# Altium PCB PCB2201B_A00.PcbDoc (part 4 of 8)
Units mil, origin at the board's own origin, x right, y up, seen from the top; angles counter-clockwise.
Board outline 4523.63 x 2358.23 mil, 6 copper layers (Top Layer, Signal Layer 2, Signal Layer 3, Signal Layer 4, Signal Layer 5, Bottom Layer), stack 61.221 mil thick; 383 components, 308 nets, 1386 pads, 1147 vias.
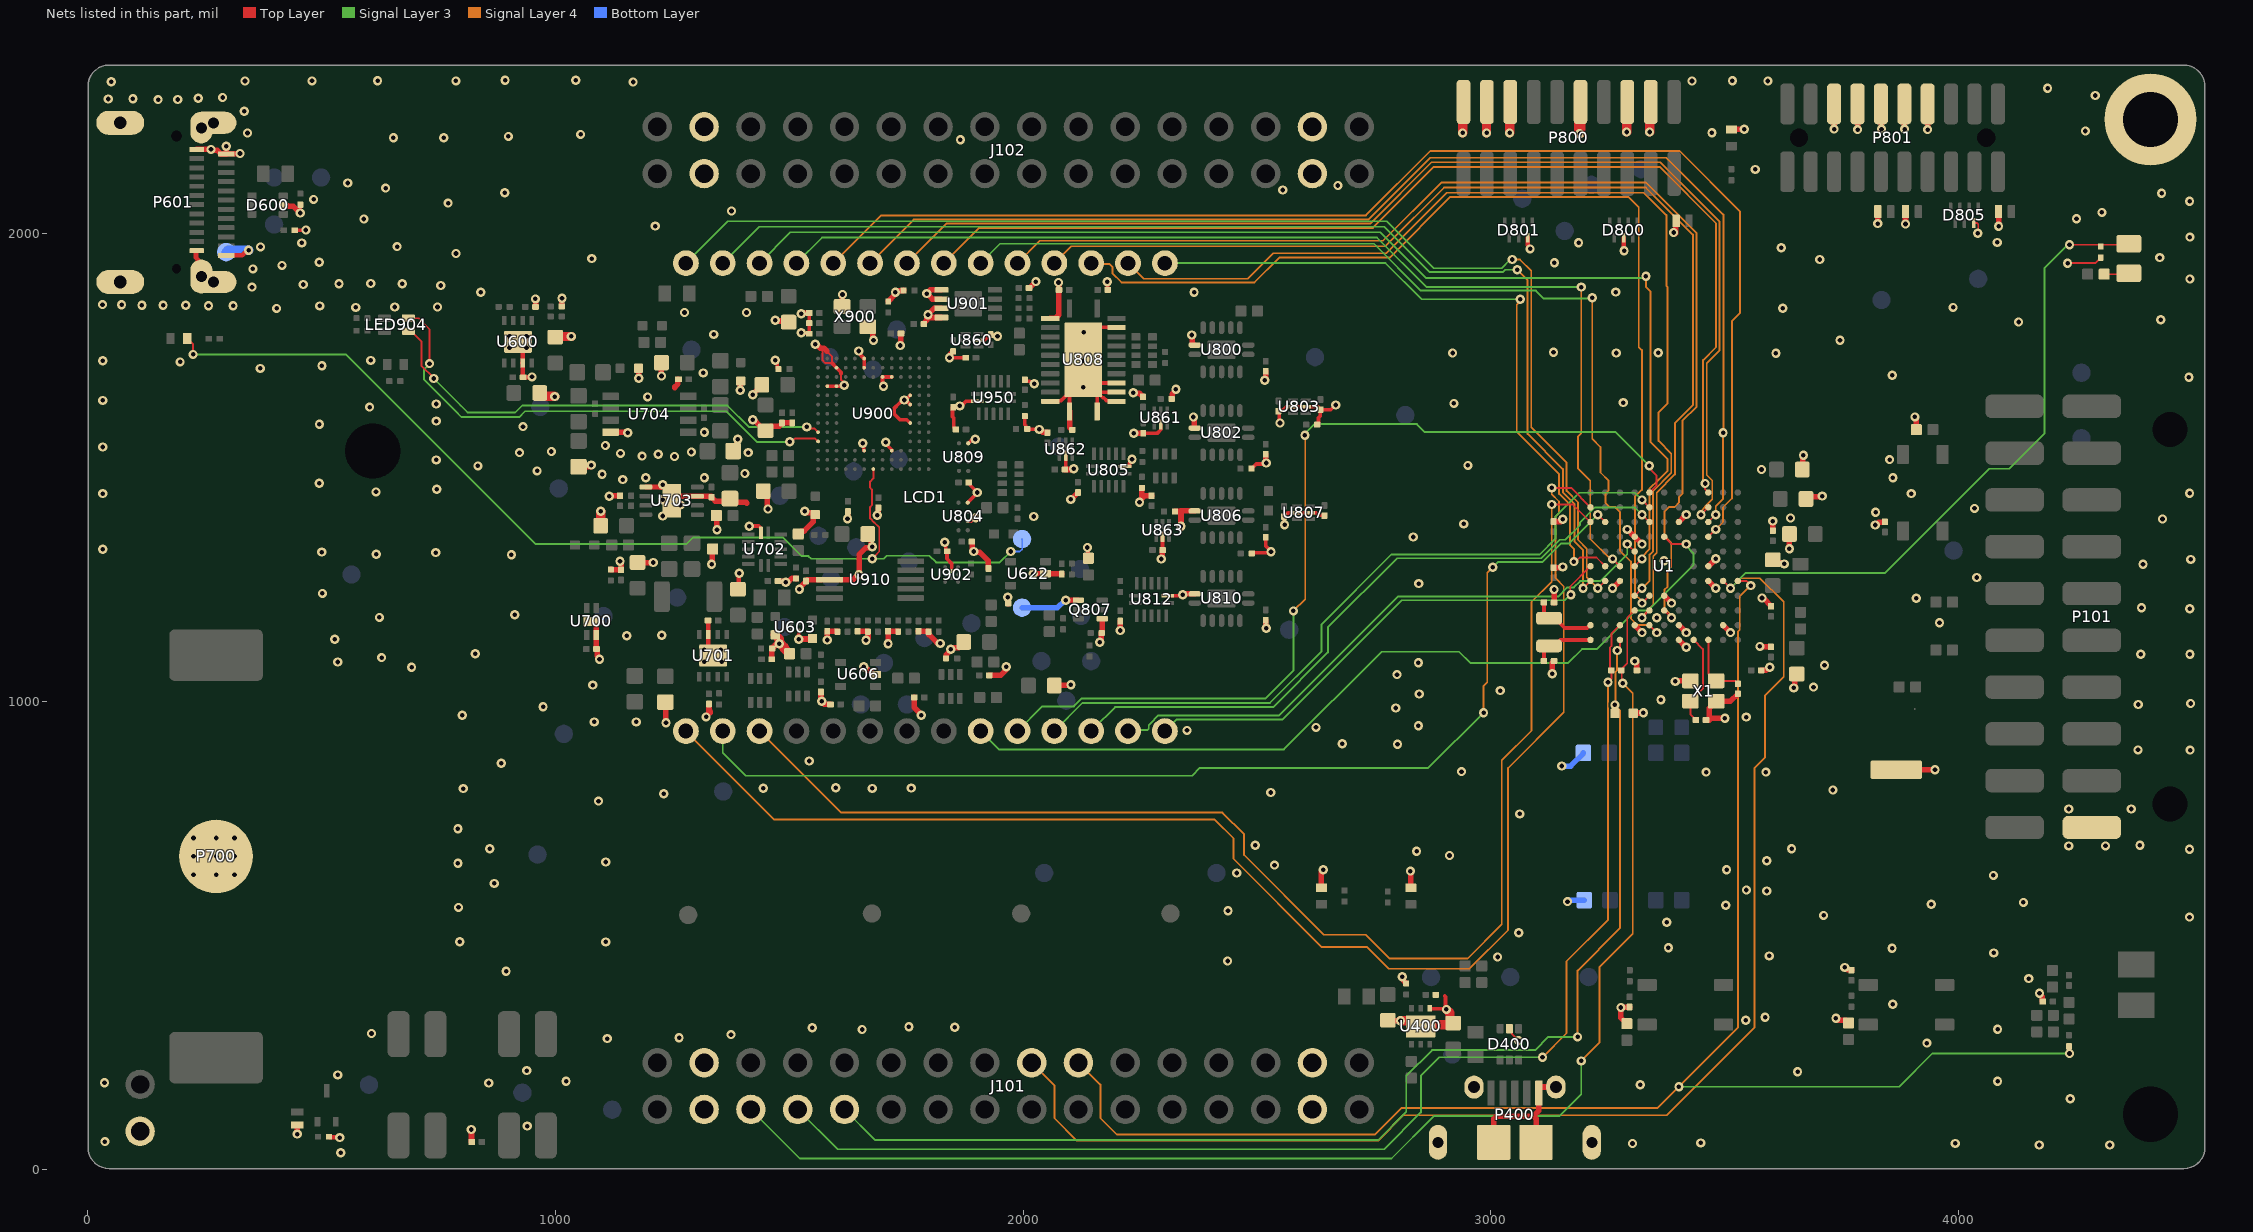
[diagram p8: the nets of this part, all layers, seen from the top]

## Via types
v1: diameter 19.68, hole 9.84, Top Layer to Bottom Layer, tented both sides, 768 vias
v2: diameter 20, hole 9.84, Top Layer to Bottom Layer, tented both sides, 379 vias

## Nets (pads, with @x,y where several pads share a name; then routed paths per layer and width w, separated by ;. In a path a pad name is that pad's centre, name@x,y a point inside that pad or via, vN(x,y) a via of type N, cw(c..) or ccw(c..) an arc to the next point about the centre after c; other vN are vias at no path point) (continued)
GND: C3.2 C4.2 C5.2 C6.2 C8.2 C9.2 C10.2 C13.2 C14.2 C15.2 C16.2 C40.2 C102.2 C103.2 C199.2 C200.2 C401.2 C402.2 C417.2 C418.2 C419.2 C420.2 C421.2 C422.2 C423.2 C600.2 C602.2 C607.2 C608.2 C609.2 C610.2 C611.2 C621.2 C625.2 C632.2 C635.2 C638.2 C641.2 C652.2 C653.2 C655.2 C660.2 C673.2 C674.2 C700.2 C701.2 C702.2 C703.2 C705.2 C706.2 C707.2 C708.2 C714.2 C720.2 C724.2 C728.2 C729.2 C730.2 C731.2 C800.2 C803.2 C804.2 C805.2 C806.2 C807.2 C808.2 C809.2 C810.2 C827.2 C828.2 C860.2 C861.2 C862.2 C863.2 C864.2 C865.2 C866.2 C867.2 C868.2 C869.2 C870.2 C900.2 C901.2 C902.2 C903.2 C904.2 C905.2 C906.2 C907.2 C908.2 C909.2 C910.2 C911.2 C914.2 C921.2 C922.2 C924.2 C925.2 C926.2 C927.2 C950.2 C951.2 D400.2 D600.2 D703.2 D800.6 D801.7 D805.7 D806.2 D807.2 D808.2 D809.2 J101.3 J101.4 J101.29 J101.30 J102.3 J102.4 J102.29 J102.30 LED100.2 LED101.2 LED900.2 M1.1 P101.1 P400.5 P400.6 P400.7 P400.8 P400.9 P400.10 P400.11 P601.25@70.87,2237.01 P601.26@70.87,1896.85 P601.27@244.09,2225.39 P601.27@269.69,2237.01 P601.28@244.09,1908.46 P601.28@269.69,1896.85 P601.A1 P601.A12 P601.B1 P601.B12 P700.2 P800.3 P800.5 P800.9 P800.15 P800.17 P800.19 P801.7 P801.9 P801.11 P801.13 P801.15 Q807.1 Q807.4 R7.1 R104.2 R105.2 R199.2 R240.1 R244.1 R407.1 R602.1 R620.1 R621.1 R623.1 R628.2 R631.1 R634.1 R637.1 R640.1 R674.2 R688.2 R691.2 R703.1 R705.1 R706.1 R707.1 R708.1 R718.1 R760.1 R763.1 R767.1 R771.1 R792.1 R807.2 R808.2 R814.1 R817.1 R839.1 R850.1 R851.1 R852.1 R853.1 R930.2 R931.2 R950.2 R981.2 ST701.1 TPJ614.1 TPJ913.1 U1.C7 U1.D4 U1.F9 U1.G3 U1.G9 U1.H6 U1.K4 U1.K7 U1.K10 U1.L7 U400.1 U400.7 U600.3 U600.9 U603.A1 U606.2 U622.2 U700.2 U700.5 U701.3 U701.9 U702.7 U703.3 U703.5 U703.9 U704.4 U800.7 U802.7 U803.2 U803.5 U804.B1 U804.D1 U805.7 U806.7 U807.2 U807.5 U808.2 U808.11 U808.12 U808.13 U808.14 U808.15 U808.16 U808.22 U808.25 U809.D1 U810.7 U812.7 U860.2 U861.2 U862.2 U863.2 U900.C5 U900.C8 U900.F3 U900.H3 U900.J3 U900.K11 U900.K12 U900.L5 U900.L6 U900.M8 U900.M11 U900.N8 U901.1 U901.2 U901.3 U901.4 U902.B2 U910.3 U950.7 X1.2 X1.4 X900.2 X900.4 | length 9025.5
  Top Layer w3.94: 1571.85,1752.95 1571.85,1729.19 1577.62,1723.43 1585.77,1723.43 1591.54,1723.43 ; 1580.71,1749.02 1591.54,1738.19 1591.54,1729.19 ; C638.2@1581.69,1150.59 C638.2@1582.19,1150.1 ; R637.1@1602.85,1150.1 1603.05,1150.3 R637.1@1603.35,1150.59 ; 1611.22,1700.76 1611.22,1687.44 1618.05,1680.61 v2(1618.05,1676.26) ; v1(3189.42,2213.38) 3189.42,2215.34 v1@3189.62,2215.54 ; D805.7@4031.5,2023.03 4032.87,2023.03 4033.27,2022.64 4039.17,2022.64 4041.48,2020.33 4041.48,2002.11 v1(4040.35,2000.98) ; 1591.54,1723.43 1591.54,1729.19 ; 1591.54,1723.43 1591.54,1729.19
  Top Layer w4: C423.2@2779.72,318.98 2780.3,318.41 2780.87,317.83 v1(2806.65,317.83) ; D400.2@3039.37,301.18 3044.73,295.82 3044.73,289.91 v1(3059.05,275.59) ; v1(4232.28,1937.01) 4291.34,1937.01 R199.2@4303.15,1948.82
  Top Layer w7.87: R621.1@443.71,2007.35 467,2007.35 v1(467.52,2007.87) ; v1(455.43,2044.1) 455.57,2044.24 455.57,2061.87 R620.1@455.71,2062.01 ; v2(1414.97,1375.16) 1415.09,1375.28 1435.35,1375.28 1439.96,1370.67 U702.7@1439.96,1360.63 ; C900.2@1441.93,1677.17 C900.2@1443.9,1677.17 ; v2(1470.47,1729.33) 1470.47,1726.05 1474.61,1721.92 1474.61,1712.99 1476.97,1710.63 R763.1@1477.36,1710.63 ; U603.A1@1520.67,1151.57 1520.44,1151.35 1520.44,1142.77 1519.69,1142.01 1519.69,1132.94 v2(1521.07,1132.94) ; v2(1526.1,1787.95) 1526.99,1787.07 1542.38,1787.07 C904.2@1543.27,1786.18 C905.2@1543.27,1808.86 C906.2@1543.27,1830.47 ; U900.K12@1581.69,1674.21 U900.K11@1601.38,1674.21 1616.01,1674.21 v2(1618.05,1676.26) ; 1591.54,1723.43 U900.M11@1601.38,1713.58 1611.22,1703.74 1611.22,1700.76 ; v2(1648.86,1749.2) 1647.64,1750.42 1645.79,1750.42 1645.79,1747.91 U900.N8@1660.43,1733.27 U900.M8@1660.43,1713.58 ; v2(1657.48,1552.17) 1659.8,1549.85 1659.8,1537.05 U900.C8@1660.43,1536.42 ; v2(1701.77,1674.21) 1699.8,1676.18 U900.L6@1699.8,1693.9 U900.L5@1719.49,1693.9 ; v2(1706.59,1554.29) 1706.59,1551.01 1719.49,1538.11 U900.C5@1719.49,1536.42 ; v2@1750,1645.67 U900.J3@1758.86,1654.53 ; U900.F3@1758.86,1595.47 1751.69,1602.64 1736.87,1602.64 1724.54,1614.97 1724.54,1626.63 1736.78,1638.87 1736.97,1638.87 1742.78,1644.69 1749.02,1644.69 U900.H3@1758.86,1634.84 ; v2(1832.68,1340.55) 1835,1338.23 1835,1323.8 C914.2@1837.36,1321.44 ; C914.2@1837.73,1321.44 C914.2@1837.36,1321.44 ; v2@1842.82,1734.83 C863.2@1877.76,1734.8 ; U902.B2@1847.44,1279.53 1847.37,1279.6 1847.37,1295.46 1837.36,1305.46 C914.2@1837.36,1321.44 ; C911.2@1849.13,1628.94 1849.13,1608.96 1852.08,1606 1852.08,1586.15 1853.35,1584.88 1853.35,1584.09 1855.71,1581.73 C909.2@1856.5,1581.73 ; C911.2@1850.82,1629.33 1852.1,1630.61 1863.88,1630.61 v2(1865.16,1631.89) 1868.44,1631.89 1878.28,1641.73 U950.7@1902.17,1641.73 ; U804.B1@1881.89,1385.83 1882.12,1386.05 1888.68,1386.05 1895.34,1392.72 v2(1898.62,1392.72) ; U804.D1@1881.89,1425.2 1881.89,1425.52 1902.56,1446.19 v2(1902.56,1446.85) 1887.01,1462.4 1887.01,1466.14 1884.65,1468.5 C810.2@1883.86,1468.5 ; U809.D1@1882.87,1552.17 1883.19,1552.17 1889.73,1558.7 1895.32,1558.7 v2(1897.64,1561.02) ; U860.2@1904.49,1772.01 1916.72,1772.01 1922.46,1777.76 1925.2,1777.76 1931.1,1783.66 C862.2@1931.1,1784.45 1933.07,1782.48 1943.42,1782.48 v2(1945.39,1780.52) ; R950.2@2003.94,1610.24 2003.94,1591.73 2006.1,1589.57 2006.1,1585.04 2008.46,1582.68 R981.2@2008.86,1582.68 2009.35,1582.19 2033.96,1582.19 v2(2034.45,1581.69) ; C950.2@2003.94,1687.99 2003.94,1687.2 2006.3,1684.84 2014.63,1684.84 2020.34,1679.13 v2(2023.62,1679.13) ; U808.11@2058.27,1641.73 2059.84,1643.31 2081.3,1643.31 2086.39,1648.4 U808.25@2099.41,1661.42 ; C860.2@2089.57,1496.06 2091.54,1498.03 U862.2@2091.54,1525.59 ; U808.12@2099.41,1620.28 U808.25@2099.41,1661.42 ; v2(2129.92,1789.37) 2140.36,1799.81 2199.01,1799.81 U808.22@2199.61,1799.21 ; v1(2137.68,1329.45) 2138.74,1328.39 2138.74,1307.48 R691.2@2139.8,1306.42 ; U808.13@2158.46,1620.28 U808.25@2158.46,1661.42 ; v2(2180.12,1897.64) 2180.61,1897.15 2180.61,1880.41 C806.2@2181.1,1879.92 ; U808.14@2199.61,1641.73 2198.03,1643.31 2178.54,1643.31 2172.47,1649.38 2170.5,1649.38 2160.43,1659.45 U808.25@2160.43,1661.42 ; U808.15@2199.61,1661.42 U808.25@2160.43,1661.42 ; U808.16@2199.61,1681.1 2137.79,1681.1 v2(2128.94,1672.24) ; U805.7@2217.91,1502.76 2227.36,1502.76 2227.36,1508.81 2232.99,1514.44 v2(2232.99,1517.72) ; C864.2@2256.89,1573.82 2287.25,1573.82 2294.29,1580.86 U861.2@2294.29,1592.52 ; C866.2@2298.23,1323.82 2298.23,1345.47 U863.2@2298.23,1352.36 ; U812.7@2309.45,1226.38 2339.57,1226.38 v2(2341.54,1228.35) ; R807.2@2488.19,1498.03 2488.58,1498.03 2498.24,1507.69 2517.09,1507.69 v2(2519.41,1510.01) ; R808.2@2488.94,1316.69 2490.71,1318.46 2528.11,1318.46 v1(2529.89,1320.24) 2529.89,1321.3 2518.7,1332.48 C809.2@2518.7,1351.38 ; v1(2549.21,1595.47) 2547.49,1597.19 2547.49,1619.15 C869.2@2545.77,1620.88 2545.77,1621.66 2548.13,1624.03 2557.1,1624.03 2562.99,1629.92 U803.2@2576.77,1629.92 U803.5@2604.33,1629.92 2630.71,1629.92 2635.83,1624.8 C807.2@2635.83,1624.02 ; v1(2558.99,1378.01) 2558.32,1378.67 2558.32,1394.81 C870.2@2557.66,1395.48 2557.66,1396.27 2563.56,1402.18 2566.29,1402.18 2568.04,1403.92 U807.2@2585.82,1403.92 U807.5@2613.38,1403.92 2625.55,1403.92 2631.38,1398.09 2643.53,1398.09 C868.2@2644.17,1397.45 ; R817.1@2628.75,1591.98 2629.14,1591.98 2631.51,1594.34 2631.51,1606.9 2635.51,1610.91 2635.51,1623.7 C807.2@2635.83,1624.02 ; v1(2668.31,1633.86) 2667.63,1633.86 2657.79,1624.02 C807.2@2635.83,1624.02 ; U400.1@2869.57,344.53 2869.57,344.39 2870.55,343.41 v1@2903.68,343.41 ; 2901.1,370.98 2902.95,369.13 2902.95,344.13 v1@2903.68,343.41 ; v1(2904.8,342.28) v1@2903.68,343.41 ; U808.25@2099.41,1661.42 2110.24,1672.24 v2(2128.94,1672.24) ; v2(2128.94,1672.24) 2149.61,1672.24 U808.25@2160.43,1661.42
  Top Layer w9.84: U703.5@1193.9,1458.66 v2@1225.39,1458.66 ; C702.2@1326.77,1173.23 1327.76,1172.24 U701.3@1327.76,1143.7 1327.76,1108.27 U701.9@1337.6,1098.43 ; C703.2@1390.75,1240.16 1392.15,1241.56 1392.15,1272.67 1393.55,1274.07 1393.55,1274.43 v2(1393.83,1274.72) ; R623.1@1463.58,1116.14 1464.96,1117.52 1465.35,1117.52 1469.91,1122.07 1472.66,1122.07 1477.39,1122.07 1477.76,1122.45 v2(1479.33,1124.02)
  Top Layer w10: P601.B1@234.25,1963.58 233.11,1963.58 232.8,1963.27 232.8,1948.82 236.97,1944.65 236.97,1915.59 P601.28@244.09,1908.46 ; P601.A12@297.24,1953.74 331.47,1953.74 342.5,1964.76 v1(345.12,1964.76) ; R792.1@517.48,70.16 518.37,69.27 539.11,69.27 v1(540,68.39) ; U600.9@920.28,1769.69 931.1,1758.86 931.1,1723.11 U600.3@930.57,1723.64 ; U600.3@931.1,1722.44 931.1,1693.58 C600.2@931.56,1693.13 931.94,1693.51 950.4,1693.51 v1(950.79,1693.9) ; D801.7@3078.47,1991.81 D801.7@3078.74,1991.54 3078.74,1975.06 3083.66,1970.14 v1(3083.66,1967.52) ; D800.6@3283.46,1991.54 3283.46,1964.57 v1(3284.45,1963.58)
  Top Layer w11.81: P601.B12@234.25,2180.12 v1(264.76,2180.12) ; v1@266.73,2178.15 267.19,2178.61 277.69,2178.61 286.02,2170.28 P601.A1@297.24,2170.28 ; v1(297.24,2187.01) P601.A1@297.24,2170.28 ; v1(326.77,2171.26) 326.28,2170.77 297.74,2170.77 P601.A1@297.24,2170.28 ; D600.2@419.29,2061.02 420.77,2059.55 428.56,2059.55 429.54,2058.56 440.85,2058.56 455.31,2044.1 v1(455.43,2044.1) ; D703.2@448.94,95.39 449.09,95.25 449.09,76.07 v1(449.23,75.92) ; v1(958.02,1860.63) 958.92,1859.74 958.92,1843.72 C602.2@958.13,1843.72 ; R602.1@1014.23,1844.7 1014.23,1861.68 v1(1014.76,1862.2) ; R767.1@1050.2,1501.97 1050.69,1501.48 1076.99,1501.48 v2(1076.99,1505.57) ; U700.5@1077.76,1171.26 1083.66,1171.26 1087.6,1167.32 U700.2@1087.6,1142.72 1087.6,1112.6 1087.99,1112.2 C708.2@1088.58,1112.2 1089.37,1112.2 1089.76,1111.81 1089.76,1097.96 1094.88,1092.85 v2(1094.88,1090.63) ; v2(1116.14,1438.7) v2@1116.14,1439.96 ; v2@1116.14,1439.96 C728.2@1138.78,1439.96 ; U704.4@1118.88,1575.79 1119.37,1575.3 1155.02,1575.3 v2(1155.51,1574.8) ; R760.1@1119.09,1282.48 1119.09,1282.09 1119.49,1281.69 1121.06,1281.69 1121.26,1281.5 C701.2@1140.75,1281.5 1141.14,1281.89 1141.14,1295.62 1138.78,1297.98 v2(1138.78,1300.2) ; C700.2@1176.18,1297.24 v2(1209.65,1297.24) ; C720.2@1178.15,1712.6 1178.64,1712.11 1178.64,1691.44 v2(1179.13,1690.94) ; v2@1225.39,1458.66 v2(1230.31,1463.58) ; v2(1227.36,1695.87) C731.2@1227.36,1724.41 ; R703.1@1235.55,998.94 1236.26,998.23 1236.26,955.63 v1(1236.97,954.92) ; 1255.91,1670.28 1255.91,1672.49 1262.6,1679.18 1262.6,1688.58 1262.99,1688.98 C730.2@1263.78,1688.98 ; v2(1267.72,1420.28) 1257.87,1420.28 U703.9@1249.02,1429.13 1258.86,1438.98 U703.3@1304.13,1438.98 1333.46,1438.98 1334.65,1437.8 C729.2@1334.65,1437.01 1334.65,1436.22 1342.48,1428.39 R718.1@1373.74,1428.39 ; v1(1322.72,967.32) 1322.72,969.45 1328.74,975.48 C705.2@1328.74,995.08 1329.13,994.69 1329.13,981.54 1331.88,978.79 1331.88,976.57 ; v1(1334.41,1293.66) v1@1335.57,1294.82 ; v1@1335.71,1294.97 v1@1335.57,1294.82 ; R705.1@1336.74,1326.17 1335.57,1325.01 v1@1335.57,1294.82 ; v1@1344.6,1368.87 v1@1345.36,1368.11 ; R706.1@1344.61,1397.76 1345.36,1397.01 v1@1345.36,1368.11 ; v1@1348.23,1367.36 v1(1346.1,1367.36) v1@1345.36,1368.11 ; R718.1@1373.74,1434.06 1382.17,1425.62 1408.32,1425.62 1409.88,1424.06 ; R771.1@1380.91,1535.43 1389.18,1543.71 1389.18,1559.46 v2(1390.75,1561.02) ; v2(1395.67,1665.35) 1396.16,1665.85 1396.16,1684.55 C724.2@1396.65,1685.04 ; v2(1422.14,1655.58) 1422.14,1656.39 1440.94,1675.2 C900.2@1441.93,1675.2 ; v2(1422.24,1602.48) 1422.24,1600.39 1423.81,1598.83 1428.73,1598.83 1449.8,1577.76 1460.63,1588.58 1479.13,1588.58 1485.24,1594.69 C924.2@1485.24,1595.47 C925.2@1506.89,1595.47 ; C902.2@1444.88,1449.8 1453.5,1441.19 1453.5,1413.15 v2(1455.06,1411.58) ; C610.2@1462.87,1090.63 R623.1@1462.87,1115.04 ; R623.1@1463.86,1113.66 1464.25,1113.66 1472.66,1122.07 1473.04,1122.45 v2@1477.76,1122.45 ; v2(1470.47,1814.96) 1472.04,1813.39 1496.65,1813.39 C903.2@1499.02,1811.02 ; C707.2@1476.38,1257.87 1476.77,1257.48 1488.7,1257.48 1491.28,1254.9 v2@1493.18,1254.9 ; v2(1493.18,1255.22) v2@1493.18,1254.9 ; v2@1493.49,1254.9 v2@1493.18,1254.9 ; v2@1495.08,1254.27 1497.28,1256.47 1498.99,1256.47 1506.68,1264.16 1507.09,1263.75 1514.68,1263.75 1515.07,1263.36 R708.1@1515.07,1262.96 ; R707.1@1519.7,1358.35 1525.6,1364.25 1531.93,1364.25 1552.17,1384.49 C901.2@1552.17,1403.54 ; v2(1521.07,1132.94) 1521.07,1133.86 C608.2@1549.21,1133.86 ; v2(1522.19,1240.48) 1522.19,1242.7 1539.37,1259.88 1539.37,1260.83 U910.3@1586.61,1260.83 1636.77,1260.83 1647.36,1271.42 v2(1649.58,1271.42) 1649.58,1314.4 1664.32,1329.14 1675.88,1329.14 v2(1677.44,1330.71) ; v2(1526.15,1828.77) 1527.46,1830.08 1542.87,1830.08 C906.2@1543.27,1830.47 ; v2(1533.27,1407.06) 1535.49,1407.06 1539.01,1403.54 C901.2@1552.17,1403.54 ; v2(1555.99,1763.89) 1558.21,1763.89 1566.68,1755.41 1574.31,1755.41 1580.71,1749.02 ; C901.2@1556.1,1399.61 C901.2@1552.17,1403.54 ; C621.2@1567.91,1020.67 1568.31,1020.28 1568.31,1004.77 1569.88,1003.2 v2(1569.88,1000.98) 1569.88,1000.03 1575.43,994.49 1588.19,994.49 C660.2@1588.58,994.09 ; v1(1581.69,1131.62) C638.2@1581.69,1150.59 ; C638.2@1582.19,1150.1 R637.1@1602.85,1150.1 ; R637.1@1602.76,1150.59 1603.05,1150.3 1603.35,1150 R637.1@1603.35,1149.61 ; X900.4@1613.19,1839.79 1613.68,1840.28 1613.68,1869.59 v2(1614.17,1870.08) ; v2(1625,1390.75) 1625.59,1391.34 1625.59,1406.1 C927.2@1625.98,1406.5 ; C641.2@1646.65,1150.59 1646.65,1150.49 1647.05,1150.1 1667.91,1150.1 1668.31,1149.7 R640.1@1668.31,1149.61 1668.7,1149.21 1668.7,1137.01 1664.37,1132.68 v2(1664.37,1130.91) ; v1(1659.82,1074.37) 1661.88,1074.37 1670.3,1065.95 1673.23,1065.95 1679.13,1060.04 1683.07,1060.04 U606.2@1685.04,1058.07 ; C921.2@1668.31,1358.27 1675.88,1350.7 1675.88,1332.98 v2@1677.8,1331.06 ; X900.2@1668.48,1799.8 1670.59,1799.8 1679.05,1791.34 1679.05,1774.14 1680.56,1772.64 v1(1680.56,1772.47) ; v2(1688.55,1397.96) 1689.86,1397.96 1690.55,1398.65 C926.2@1690.55,1414.37 ; v2(1711.61,1124.02) C635.2@1711.61,1150.59 1711.61,1150.49 1712.01,1150.1 1732.87,1150.1 1733.27,1149.7 R634.1@1733.27,1149.61 ; R931.2@1711.98,1855.15 1711.98,1855.54 1725.8,1869.36 1725.8,1873.43 v2(1727.36,1875) 1729.58,1875 1732.85,1878.27 1744.21,1878.27 R930.2@1744.61,1878.66 ; v1(1737.64,1761.02) 1738.44,1761.83 1738.44,1786.14 1738.84,1786.54 C910.2@1739.25,1786.54 ; C674.2@1767.56,1009.13 1767.56,987.9 1782.48,972.98 v1(1782.48,970.85) ; C632.2@1776.57,1150.59 1797.64,1150.59 1798.62,1149.61 1798.62,1143.03 1815.7,1125.95 1821.27,1125.95 v2(1822.83,1124.38) ; C908.2@1788.15,1807.09 1788.94,1807.09 1789.33,1807.48 1789.33,1809.9 1794.69,1815.27 1794.69,1818.84 1795.28,1819.42 1795.28,1825.21 v2(1796.93,1826.87) ; v2@1796.26,1826.77 1810.04,1840.55 U901.3@1825.79,1840.55 ; v2@1796.93,1826.77 1797.32,1826.77 1803.22,1820.87 U901.4@1825.79,1820.87 ; U901.2@1825.79,1860.24 1806.1,1860.24 v2(1794.29,1872.05) 1802.17,1879.92 U901.1@1825.79,1879.92 ; R674.2@1835.63,1092.52 1836.02,1092.52 1836.42,1092.91 1836.42,1100.35 1845.78,1109.71 v2(1845.78,1111.93) ; v2@1842.8,1737.07 v2(1842.8,1734.85) 1844.36,1736.42 1844.36,1741.8 1850.67,1748.11 R850.1@1850.67,1748.5 ; v2@1846.46,1110.39 1851.23,1115.16 C625.2@1860.75,1115.16 ; C625.2@1863.19,1115.16 C625.2@1860.75,1115.16 ; C625.2@1873.07,1127.48 1873.07,1126.5 1863.23,1116.65 1862.24,1116.65 C625.2@1860.75,1115.16 ; C804.2@1890.55,1341.85 1891.34,1341.85 1891.73,1341.46 1891.73,1326.03 1893.12,1324.65 1893.12,1322.43 1896.25,1319.3 1907.08,1319.3 1925.79,1300.59 1925.79,1284.84 C652.2@1926.18,1284.45 ; C673.2@1928.11,1056.26 1952,1056.26 1962.55,1066.81 1962.55,1073.18 v1(1964.06,1074.69) ; v2(1967.52,1223.43) 1968.01,1222.93 1968.01,1210.04 1968.41,1209.65 R688.2@1968.5,1209.65 ; C951.2@2012.8,1883.86 2013.58,1883.86 2027.36,1897.64 v1(2027.56,1897.64) ; v2(2021.71,1273.07) 2021.99,1273.34 2047.95,1273.34 U622.2@2048.23,1273.62 2048.72,1273.13 2082.28,1273.13 C653.2@2082.68,1272.64 C653.2@2082.68,1272.64 ; v2(2034.45,1581.69) 2036.66,1581.69 2042.37,1575.98 2051.77,1575.98 2052.17,1575.59 C861.2@2052.17,1574.8 ; U808.2@2058.27,1818.9 2068.9,1818.9 2076.77,1826.77 C808.2@2076.77,1879.92 2076.67,1879.92 2076.28,1880.32 2076.28,1895.18 v2(2075.79,1895.67) ; C655.2@2066.93,1034.45 2067.64,1035.16 2101.65,1035.16 v1(2102.36,1035.87) ; C860.2@2089.57,1496.06 2104.08,1496.06 2106.05,1498.03 v2(2108.27,1498.03) ; v2(2091.54,1216.54) Q807.4@2118.11,1216.54 ; U808.12@2099.41,1620.28 2099.8,1619.88 2099.8,1585.83 2104.92,1580.71 R852.1@2105.32,1580.71 ; v2(2102.36,1432.09) C800.2@2117.13,1446.85 ; v2(2164.04,1127.25) 2164.04,1129.47 2167.52,1132.95 2167.52,1146.26 2168.31,1147.05 2169.09,1147.05 2169.09,1153.35 2169.29,1153.54 Q807.1@2169.29,1177.17 ; C828.2@2207.68,1172.24 2207.89,1172.03 2207.89,1152.34 v2(2208.11,1152.12) ; v2(2235.24,1660.43) 2236.8,1658.87 2248.89,1658.87 2255.2,1652.56 2255.98,1652.56 2256.38,1652.17 C865.2@2256.38,1651.38 ; v2(2236.74,1573.3) 2237,1573.56 2256.63,1573.56 C864.2@2256.89,1573.82 ; R814.1@2254.09,1456.31 2254.09,1433.73 2249.02,1428.65 v2(2249.02,1426.44) 2250.58,1428 2250.58,1430.7 2260.08,1440.2 C867.2@2274.8,1440.2 ; v2(2295.28,1304.84) 2295.28,1305.37 2297.05,1307.14 2297.05,1323.43 2297.44,1323.82 C866.2@2298.23,1323.82 ; R851.1@2317.8,1646.93 2318.19,1646.93 2318.58,1647.32 2318.58,1647.72 2318.7,1647.83 2318.7,1657.04 2326.77,1665.11 v2(2326.77,1667.32) ; R853.1@2324.8,1406.5 2325.2,1406.89 2336.15,1406.89 2336.74,1407.48 ; v2(2337.49,1374.89) 2337.49,1378.56 2337.6,1378.67 2337.6,1406.62 2336.74,1407.48 ; v2(2341.54,1228.35) 2343.75,1228.35 2345.72,1230.32 U810.7@2367.13,1230.32 ; v2(2360.24,1783.46) 2361.8,1781.9 2361.8,1761.81 U800.7@2367.13,1761.81 ; v2(2364.17,1608.27) 2365.65,1606.79 2365.65,1584.65 U802.7@2367.13,1584.65 ; U806.7@2367.13,1407.48 2336.74,1407.48 ; v2(2516.73,1687.01) 2516.73,1689.22 2518.31,1690.8 2518.31,1705.31 C803.2@2518.7,1705.71 ; C827.2@2518.7,1174.21 2519.05,1173.86 2519.05,1156.85 v2(2519.41,1156.5) ; C805.2@2518.7,1528.54 2519.05,1528.19 2519.05,1510.36 v2(2519.41,1510.01) ; LED101.2@2637.8,602.2 2637.8,634.98 2641.59,638.78 v1(2641.59,640.91) ; C423.2@2780.3,318.41 2806.08,318.41 v1(2806.65,317.83) ; v1(2810.55,412.09) 2812.06,410.58 2812.06,404.75 2818.66,398.15 R407.1@2818.66,397.76 ; v1(2827.76,637.8) 2828.25,637.3 2828.25,614.5 ; LED100.2@2828.74,602.2 2828.25,602.69 2828.25,614.5 ; 2828.74,614.01 2828.25,614.5 ; P400.10@3005.91,58.35 3005.91,108.27 3011.81,114.17 3090.55,114.17 ; P400.11@3096.46,58.35 3096.46,108.27 3090.55,114.17 ; v1(3130.91,1059.49) 3130.91,1082.68 C422.2@3134.84,1086.61 ; C13.2@3133.86,1286.42 3152.02,1286.42 v1(3153.54,1287.93) ; C9.2@3133.86,1384.84 3148.65,1384.84 v1(3153.55,1389.74) ; C421.2@3134.84,1211.61 v1@3134.84,1233.3 ; v1@3134.91,1233.34 v1(3134.91,1239.72) ; P400.7@3138.78,176.46 3102.38,176.46 P400.5@3102.38,163.66 3102.38,126 3090.55,114.17 ; v1(3259.8,1242.1) U1.G3@3275.59,1257.87 ; R105.2@3290.32,311.81 3277.2,324.92 3277.2,345.97 v1(3277.71,346.47) 3278.17,346.94 3295.94,346.94 3296.34,347.33 C103.2@3296.34,347.4 ; v1(3291.32,1368.15) U1.D4@3307.09,1352.36 ; C40.2@3304.13,975.1 3304.77,975.74 3325.15,975.74 v1(3325.79,976.38) ; U1.K4@3307.09,1163.39 v1(3322.86,1147.59) ; U1.D4@3307.09,1352.36 v1(3322.85,1336.59) ; C14.2@3312.01,1066.93 v1@3312.01,1081.68 ; U1.H6@3370.08,1226.38 v1(3385.85,1210.59) ; v1(3390.22,2002.44) 3392.66,2000 3393.7,2000 3394.68,2000.98 3394.68,2026.57 D809.2@3395.67,2027.56 ; v1(3393.7,1043.31) 3394.68,1044.29 X1.2@3426.18,1044.29 ; U1.L7@3401.57,1131.89 v1(3417.34,1116.1) ; U1.K7@3401.57,1163.39 v1(3417.34,1147.59) ; U1.C7@3401.57,1383.86 v1(3417.37,1399.63) ; U1.G9@3464.57,1257.87 v1(3480.34,1242.08) ; U1.F9@3464.57,1289.37 v1(3480.36,1305.14) ; U1.K10@3496.06,1163.39 v1(3511.83,1147.59) ; v1(3499.99,964.57) 3470.47,964.57 3466.54,960.63 3466.54,986.22 X1.4@3481.3,1000.98 3511.81,1000.98 C418.2@3527.56,1016.73 ; LED900.2@3513.78,2222.44 3514.09,2222.76 3540.87,2222.76 v1(3541.18,2223.07) ; v1(3574.8,1118.11) 3575.79,1117.13 C5.2@3598.43,1117.13 ; C4.2@3577.76,1066.93 3578.15,1067.32 3587.74,1067.32 3593.78,1073.37 v1(3595.91,1073.37) ; v1(3579.14,1221.45) 3580.65,1219.95 3583.01,1219.95 3598.43,1204.53 C6.2@3598.43,1203.74 ; C16.2@3602.36,1303.15 3608.73,1296.78 3626.45,1296.78 3627.95,1295.28 v1(3626.97,1294.29) ; C15.2@3602.36,1365.16 v1(3602.36,1385.83) ; v1(3637.8,1326.77) C10.2@3637.8,1358.27 ; v1(3647.2,1029.33) 3648.71,1030.84 3648.71,1054.22 C3.2@3653.54,1059.06 ; C401.2@3665.35,1496.06 3666.52,1497.23 3666.52,1525.34 v1(3667.7,1526.51) ; C402.2@3681.1,1441.93 3681.1,1439.66 3683.07,1437.7 3706.3,1437.7 v1(3707.81,1439.2) ; v1(3733.27,2223.43) P801.15@3733.27,2277.22 ; v1(3737.2,323.18) 3739.34,323.18 3743.39,319.13 3758.15,319.13 R104.2@3764.06,313.23 ; v1(3755.91,432.09) 3758.04,432.09 3762.84,427.28 3770.04,427.28 3770.43,426.89 C102.2@3770.43,426.1 ; P801.13@3783.27,2277.22 3783.37,2277.13 3783.37,2222.54 v1(3783.46,2222.44) ; v1(3826.77,2021.65) D806.2@3826.77,2047.24 ; P801.11@3833.27,2277.22 3833.96,2276.54 3833.96,2224.11 v1(3834.65,2223.43) ; C200.2@3866.14,854.33 v1(3948.82,854.33) ; P801.9@3883.27,2277.22 3883.56,2276.93 3883.56,2223.72 v1(3883.86,2223.43) ; v1(3885.83,2020.67) D807.2@3885.83,2047.24 ; v1(3933.07,2222.44) 3933.17,2222.54 3933.17,2277.13 P801.7@3933.27,2277.22 ; D808.2@4084.65,2047.24 4084.68,2047.2 4084.68,2015.83 v1(4084.72,2015.79) ; v1(4172.13,376.97) 4172.13,374.84 4177.95,369.01 4177.95,359.68 4178.35,359.29 C199.2@4179.13,359.29
  Top Layer w12: v1(821.01,85.61) 821.43,85.19 821.43,59.35 821.73,59.06 C706.2@821.85,59.06 ; v1(3737.2,323.18) v1@3737.35,323.04 ; v1(3821.18,1377.48) 3823.26,1377.48 3828.79,1383.01 3841.47,1383.01 3841.77,1383.31 C8.2@3841.77,1384.09 ; v1(3905.97,1608.38) 3908.93,1605.42 R7.1@3908.93,1581.16
  Top Layer w19.68: C611.2@966.99,1659.66 966.99,1658.68 972.9,1652.77 998.33,1652.77 v1(999.21,1651.89) ; C607.2@1000.45,1778.76 1002.21,1780.51 v1(1034.45,1780.51) ; C714.2@1097.44,1375.98 v2(1097.44,1406.5) ; C609.2@1470.47,1142.72 1479.27,1133.92 1479.27,1124.08 v2(1479.33,1124.02) ; v2@1482.2,1124.02 1489.96,1116.25 1489.96,1113.39 R628.2@1500.98,1102.36 ; v1(2806.65,317.83) 2838.19,317.83 U400.7@2849.88,306.14 2853.21,309.47 2916,309.47 C420.2@2919.33,312.8 2918.35,312.8 2912.44,318.7 2912.44,334.65 v1(2904.8,342.28)
  Top Layer w20: v1(2939.42,2215.34) 2939.42,2283.34 P800.19@2939.62,2283.53 ; P800.17@2989.62,2283.53 2990.6,2282.55 v1(2990.6,2215.34) ; P800.15@3039.62,2283.53 3039.81,2283.34 v1(3039.81,2215.34) ; P800.5@3289.62,2283.53 3289.81,2283.34 v1(3289.81,2217.31) ; v1(3339.03,2217.31) 3339.03,2282.94 P800.3@3339.62,2283.53
  Top Layer w25: v1@3189.62,2215.54 P800.9@3189.62,2283.53
  Bottom Layer w11.81: TPJ913.1@1998.03,1200.79 2073.57,1200.79 2089.32,1216.54 v2(2091.54,1216.54) ; v1(3151.38,862.55) 3151.84,862.09 3170.2,862.09 3197.56,889.45 R240.1@3197.56,890.43 ; v1(3163.56,572.69) 3165.69,572.69 3168.79,575.79 R244.1@3199.33,575.79 ; v1(3574.8,1118.11) v1@3576.31,1119.62 ; v1(3578.03,1495.98) v1@3579.54,1494.48
  Bottom Layer w20: P601.28@244.09,1908.46 244.09,1913.83 P601.28@256.68,1926.41 ; TPJ614.1@297.15,1960.61 300.86,1964.32 344.67,1964.32 v1(345.12,1964.76)
  other v1: 542.13,35.79 4171.54,52.44 4322.48,52.44 3302.36,55.63 3992.24,55.98 3448.18,57.05 38,59.71 940.75,92.83 4238.15,151.3 3318.9,181.1 37.2,185.67 858.27,185.04 1023.62,188.98 4082.68,188.98 535.75,202.32 3655.28,209.06 939.68,211.54 3931.65,270.35 1111.54,279.92 1264.96,281.69 1375.87,288.43 607.68,290.91 1656.14,299.41 4082.6,299.76 1549.49,302.95 1854.21,304.02 1756.06,305.08 3544.69,319.23 3585.79,325.61 3858.66,353.27 4149.21,408.19 895.39,423.78 2437.09,445.75 3014.25,454.23 3594.49,456.69 4074.45,463.11 3857.24,473.03 3379.25,474.09 796.08,486.75 1108.35,486.5 3059.29,505.98 3375.71,528.66 4492.8,539.65 3710.91,543.19 2438.15,553.11 793.61,560.25 3501.85,564.8 3940.94,566.93 4137.8,570.87 3589.37,595.28 3545.79,597.4 870.24,611.57 4073.74,628.58 227.36,629.92 275.59,629.92 314.96,629.92 2456.69,633.86 3503.62,640.63 2537.4,650.59 792.28,654.45 1108.35,657.28 3589.37,660.12 227.36,669.29 275.59,669.29 314.96,669.29 2911.5,671.08 2840.99,680.29 4492.8,684.57 860.32,685.63 3642.48,685.61 4234.54,691.73 4313.28,691.73 2496.06,692.91 4386.69,692.91 227.36,708.66 275.59,708.66 314.96,708.66 792.28,728.15 3061.38,760.02 4234.54,770.47 4368.11,770.47 1092.77,787.4 1232.28,803.15 2529.35,805.93 3730.75,811.06 803.62,814.25 1677.76,814.61 1444.88,814.96 1761.02,815.32 1599.8,816.02 3459.68,849.43 3587.56,849.43 2937.01,850.39 884.76,868.11 1543.11,873.07 4382.72,896.81 4493.98,896.46 2800.16,909.09 2682.25,909.9 2350.39,938.43 2625.98,944.88 2845,948.35 1083.54,956.69 1173.54,956.69 3545.4,966.95 801.5,970.87 2796.38,986.46 974.41,988.94 4383.07,993.9 4495.04,996.02 3363.08,1003.82 2846.69,1016.34 3019.68,1023.62 3689.29,1031.1 1080.71,1035.35 2799.25,1057.8 693.43,1073.62 3712.68,1077.87 2845,1083.11 535.39,1084.61 3307.08,1086.61 629.29,1094.17 4388.39,1101.26 4493.62,1101.26 529.37,1133.5 1152.99,1140.94 1227.76,1141.65 3958.42,1168.67 3354.35,1179.09 624.69,1179.92 913.82,1185.75 4493.27,1198.7 4390.16,1200.47 3908.98,1221.02 502.8,1231.3 2845.63,1252.2 4037.95,1265.32 4393.35,1293.66 3370.05,1301.09 4495.39,1303.94 906.73,1313.86 617.85,1315.05 745.16,1318.46 501.38,1319.53 33.31,1325.55 2833.94,1351.77 2941.65,1379.76 4435.16,1390.39 3640.04,1392.52 2022.87,1395.71 3821.86,1404.53 4033.27,1412.87 33.31,1444.61 3898.21,1444.58 4492.91,1445.32 617.24,1448.15 746.93,1453.82 496.06,1466.57 1144.68,1474.41 1193.79,1478.31 1319.06,1478.55 3859.02,1478.27 1100.55,1485.71 1405.63,1487.47 961.61,1493.11 835.16,1503.78 2950.79,1504.92 746.22,1516.54 3851.86,1517.31 1185.94,1524.69 1255.17,1523.93 1220.47,1528.54 1139.76,1530.51 924.09,1532.13 1412.89,1532.26 1291.34,1533.46 992.13,1534.61 33.31,1544.17 1107.64,1547.36 1319.17,1575.71 931.54,1587.76 496.42,1592.72 746.22,1599.45 603.58,1629.46 745.87,1635.94 2920.75,1637.36 3282.52,1639.13 33.31,1643.74 1197.64,1651.18 4491.5,1692.99 3857.6,1697.6 1316.69,1702.56 369.92,1712.13 501.73,1717.8 198.78,1725.94 33.31,1728.43 606.12,1729.25 3608.86,1744.37 2917.91,1745.08 3267.64,1745.08 3357.64,1745.79 3133.7,1746.5 902.56,1755.91 938.98,1755.91 3745.98,1772.36 902.56,1780.51 938.98,1780.51 1339.02,1784.76 4127.6,1811.34 4431.26,1815.94 1276.65,1831.54 1409.17,1831.54 405,1840.39 3623.39,1840.75 574.02,1842.52 3987.64,1842.52 657.28,1843.23 748.7,1843.23 497.13,1845.71 259.44,1846.02 311.88,1846.02 117,1847.09 162.35,1847.09 210.82,1847.13 32.95,1848.54 73.7,1848.19 2365.67,1874.67 841.28,1874.9 3266.57,1875.12 352.24,1885.92 755.79,1889.29 461.69,1891.42 538.23,1893.19 605.91,1893.54 673.23,1893.19 4493.62,1903.11 354.33,1924.72 416.34,1932.17 3135.47,1937.83 496.06,1938.9 3702.76,1944.92 1078.58,1946.69 4429.13,1948.82 788.39,1957.68 3620.2,1969.72 370.52,1971.72 662.4,1972.44 458.86,1980.35 3187.2,1980.71 4081.89,1981.42 4493.62,1992.76 1213.94,2016.14 591.54,2031.5 4251.26,2032.09 4305.47,2045.55 1376.93,2048.39 771.38,2065.39 4492.91,2069.29 484.02,2073.19 4433.07,2086.61 892.56,2087.36 2554.86,2093.28 637.8,2097.44 2672.99,2102.87 557.09,2108.27 3564.57,2137.32 1866.14,2200.79 654.45,2205 762.17,2205 900.35,2207.83 1054.49,2212.09 342.67,2215.09 3472.09,2215.63 4270.39,2219.53 335.59,2261.51 151.65,2286.5 193.82,2286.85 45.35,2287.91 97.8,2288.27 237.4,2289.33 289.49,2291.1 4291.34,2295.28 4189.61,2310.59 51.73,2324.76 1166.81,2324.06 337.32,2326.18 480.47,2326.54 788.03,2326.54 3429.57,2326.18 3591.85,2326.18 620.79,2326.89 3516.02,2326.89 893.27,2327.95 1044.21,2327.95
  other v2: 1318.9,1085.63 1356.3,1085.63 829.72,1102.36 1318.9,1111.22 1354.33,1111.22 1894.65,1320.9 1230.31,1396.65 1230.31,1431.1 1746.06,1644.69 2128.94,1728.35
HFXTAL_N: C418.1 U1.L9 X1.1 | length 144.5
  Top Layer w3.94: U1.L9@3464.56,1131.95 3464.56,1059.05 3467.07,1056.55 3479.33,1044.29 X1.1@3481.3,1044.29 3521.65,1044.29 C418.1@3527.56,1038.39
HFXTAL_P: C417.1 U1.L8 X1.3 | length 195.4
  Top Layer w3.94: U1.L8@3433.06,1131.95 3452.76,1112.25 3452.76,1027.56 X1.3@3426.18,1000.98 3426.18,973.43 3437.99,961.61 C417.1@3437.99,960.63
LCD_BCAP_N: C500.2 J101.7 U1.K3 | length 2750.1
  Top Layer w3.94: v1(3250.16,1041.39) 3257.87,1049.1 3257.87,1069.88 3254.18,1073.57 3254.18,1115.67 3257.87,1119.36 3257.87,1145.77 U1.K3@3275.59,1163.39 U1.K3@3275.59,1163.39
  Signal Layer 3 w3.94: J101.7@1518.5,128.43 1603.62,43.31 2771.65,43.31 2850.39,122.05 2850.39,200.79 2889.76,240.16 v1(3110.24,240.16)
  Signal Layer 4 w3.94: v1(3110.24,240.16) 3161.42,291.34 3161.42,444.88 3250.16,533.62 3250.16,986.06 3249.45,986.77 3249.45,999.45 3250.16,1000.16 v1(3250.16,1041.39)
LCD_BCAP_P: C500.1 J101.5 U1.J4 | length 2975.2
  Top Layer w3.94: v1(3281.5,1039.37) 3279.53,1041.34 3279.53,1069.88 3291.36,1081.71 3291.36,1179.15 U1.J4@3307.09,1194.88
  Signal Layer 3 w3.94: J101.5@1418.5,128.43 1523.29,23.64 2787.42,23.64 2877.95,114.17 3145.67,114.17 3192.91,161.42 v1(3192.91,232.28)
  Signal Layer 4 w3.94: v1(3192.91,232.28) 3232.28,271.65 3232.28,433.07 3303.15,503.94 3303.15,1017.72 v1(3281.5,1039.37)
LCD_BEXT: C40.1 J101.9 U1.L3 | length 2635.3
  Top Layer w3.94: C40.1@3264.76,975.1 v1(3264.76,993.11) v1@3264.76,995.08 ; v1(3269.68,1109.25) 3275.59,1115.16 U1.L3@3275.59,1131.89
  Signal Layer 3 w3.94: J101.9@1618.5,128.43 1683.94,62.99 2758.61,62.99 2818.9,123.28 2818.9,200.11 2874.25,255.47 3094.49,255.47 3122.48,283.46 v1(3185.04,283.46)
  Signal Layer 4 w3.94: v1(3185.04,283.46) 3185.04,425.2 3275.59,515.75 3275.59,981.67 v1@3267.1,990.16 ; v1@3266,998.28 3266,1062.99 3269.68,1066.68 v1(3269.68,1109.25)
LCD_COM0: LCD1.21 U1.A9 | length 2376.7
  Top Layer w3.94: v1(3457.57,1466.21) 3457.57,1453.85 U1.A9@3464.57,1446.85
  Signal Layer 4 w3.94: LCD1.21@1830.71,1937.01 1906.03,2012.33 2747.57,2012.33 2877.95,2142.72 3360.24,2142.72 3480.86,2022.09 3480.86,1757.44 3453.19,1729.77 3453.19,1474.85 3457.57,1470.47 v1(3457.57,1466.21)
LCD_COM1: LCD1.22 U1.B9 | length 2553.1
  Top Layer w3.94: v1(3448.85,1399.59) U1.B9@3464.57,1415.31
  Signal Layer 4 w3.94: LCD1.22@1751.97,1937.01 1836.42,2021.46 2741.8,2021.46 2872.9,2152.56 3361.53,2152.56 3488.74,2025.35 3488.74,1750.55 3461.07,1722.88 3461.07,1484.36 3472.88,1472.55 3472.88,1432.65 3457.16,1416.94 3457.16,1415.14 3448.85,1406.82 v1(3448.85,1399.59)
LCD_COM2: LCD1.23 U1.C9 | length 2637.3
  Top Layer w3.94: U1.C9@3464.61,1383.86 v1(3480.35,1399.59)
  Signal Layer 4 w3.94: LCD1.23@1673.23,1937.01 1766.18,2029.96 2737.56,2029.96 2870,2162.4 3375,2162.4 3496.61,2040.79 3496.61,1575.35 v1(3496.06,1574.8) 3496.06,1433.57 3480.35,1417.85 v1(3480.35,1399.59)
LCD_COM3: LCD1.24 U1.D9 | length 2814
  Top Layer w3.94: U1.D9@3464.57,1352.36 v1(3480.35,1368.09)
  Signal Layer 4 w3.94: LCD1.24@1594.49,1937.01 1696.65,2039.17 2732.8,2039.17 2870.34,2176.71 3403.01,2176.71 3532.48,2047.24 3532.48,1830.71 3514.76,1812.99 3514.76,1434.06 3495.85,1415.14 3495.85,1383.59 v1(3480.35,1368.09)
LCD_COM4: LCD1.25 U1.F3 | length 2383.4
  Top Layer w3.94: v1(3259.85,1305.09) U1.F3@3275.59,1289.37
  Signal Layer 3 w3.94: LCD1.25@1515.75,1937.01 1570.59,1991.85 2756.18,1991.85 2861.71,1886.32 3192.42,1886.32 v1(3192.91,1885.83)
  Signal Layer 4 w3.94: v1(3192.91,1885.83) 3192.91,1573.38 3185.91,1566.38 3185.91,1498.63 3212.16,1472.39 3212.16,1347.57 3254.64,1305.09 v1(3259.85,1305.09)
LCD_COM5: LCD1.26 U1.F4 | length 2649.3
  Top Layer w3.94: v1(3322.85,1305.09) 3308.67,1290.96 v1(3322.85,1305.09)
  Signal Layer 3 w3.94: LCD1.26@1437.01,1937.01 1502.95,2002.95 2763.78,2002.95 2861.63,1905.1 3322.98,1905.1 3326.88,1909.01 v1(3331.15,1909.01)
  Signal Layer 4 w3.94: v1(3322.85,1305.09) 3322.85,1309.76 3338.58,1325.49 3338.58,1454.73 3358.27,1474.41 3358.27,1474.58 3377.35,1493.66 3377.35,1518.32 3341.13,1554.54 3341.13,1876.39 3331.15,1886.37 v1(3331.15,1909.01)
LCD_COM6: LCD1.27 U1.G1 | length 2536.1
  Top Layer w3.94: v1(3196.85,1242.09) U1.G1@3210.93,1256.18 ; U1.G1@3212.6,1257.87 U1.G1@3210.93,1256.18 ; U1.G1@3212.64,1257.83 3210.9,1256.1 U1.G1@3210.93,1256.18
  Signal Layer 3 w3.94: LCD1.27@1358.27,1937.01 1436.02,2014.76 2771.65,2014.76 2868.17,1918.25 3025.95,1918.25 3030.74,1923.04 v1(3056.05,1923.04)
  Signal Layer 4 w3.94: v1(3056.05,1923.04) 3078.3,1900.79 3078.3,1572.29 3153.67,1496.92 3153.67,1447.09 3178.15,1422.61 3178.15,1342.58 3196.85,1323.88 v1(3196.85,1242.09)
LCD_COM7: LCD1.28 U1.G2 | length 2662.8
  Top Layer w3.94: v1(3228.35,1242.09) U1.G2@3244.09,1257.87
  Signal Layer 3 w3.94: LCD1.28@1279.53,1937.01 1369.09,2026.57 2777.56,2026.57 2878.01,1926.13 3022.69,1926.13 3041.45,1944.88 v1(3045.28,1944.88)
  Signal Layer 4 w3.94: v1(3045.28,1944.88) 3061.81,1944.88 3086.18,1920.52 3086.18,1586.07 3161.67,1510.57 3161.67,1450.23 3186.02,1425.87 3186.02,1345.84 3204.85,1327.01 3204.85,1265.59 v1(3228.35,1242.09)
LCD_SEG12: LCD1.1 U1.B1 | length 3137.8
  Top Layer w3.94: v1(3129.92,1456.69) 3171.25,1456.69 U1.B1@3212.6,1415.35 ; U1.B1@3212.6,1415.35 3212.66,1415.35 U1.B1@3212.6,1415.35
  Signal Layer 4 w3.94: LCD1.1@1279.53,937.01 1468.5,748.03 2409.45,748.03 2449.8,707.68 2449.8,664.37 2638.78,475.39 2735.24,475.39 2781.5,429.13 2953.74,429.13 3036.42,511.81 3036.42,857.96 3155.51,977.05 3155.51,1246.06 3138.04,1263.54 3138.04,1396.18 3145.41,1403.56 3145.41,1427.68 3129.91,1443.18 v1(3129.92,1456.69)
LCD_SEG13: LCD1.2 U1.C2 | length 2360.8
  Top Layer w3.94: v1(3228.35,1399.59) U1.C2@3244.09,1383.86
  Signal Layer 3 w3.94: LCD1.2@1358.27,937.01 1358.27,890.75 1407.48,841.54 2361.22,841.54 2377.95,858.27 2866.14,858.27 v1(2984.25,976.38) ; v1(3003.94,1287.4) 3014.59,1298.06 3109.7,1298.06 3149.79,1338.15 3166.9,1338.15 v1(3228.35,1399.59)
  Signal Layer 4 w3.94: v1(2984.25,976.38) 2984.25,1034.02 2992.04,1041.81 2992.04,1275.51 v1(3003.94,1287.4)
LCD_SEG14: LCD1.3 U1.C1 | length 2883.4
  Top Layer w3.94: v1(3129.91,1421.26) 3175.19,1421.26 U1.C1@3212.6,1383.86
  Signal Layer 4 w3.94: LCD1.3@1437.01,937.01 1611.22,762.8 2426.18,762.8 2472.44,716.54 2472.44,672.24 2642.72,501.97 2732.28,501.97 2783.46,450.79 2949.8,450.79 3022.95,523.93 3022.95,874.32 3086.61,937.99 3086.61,1213.07 3129.91,1256.38 v1(3129.91,1421.26)
LCD_SEG28: LCD1.9 U1.D6 | length 1827.4
  Top Layer w3.94: U1.D6@3370.08,1352.36 3385.86,1336.65 v1@3417.29,1336.65 ; v1(3417.35,1336.59) v1@3417.29,1336.65 ; v1@3417.36,1336.65 v1@3417.29,1336.65
  Signal Layer 3 w3.94: LCD1.9@1909.45,937.01 1948.54,897.92 2557.37,897.92 2766.19,1106.74 2931.65,1106.74 2955.71,1082.68 3165.05,1082.68 3194.57,1112.2 3225.77,1112.2 3307.97,1194.41 3335.15,1194.41 3432.63,1291.89 3432.63,1317.48 3417.35,1332.77 v1(3417.35,1336.59)
LCD_SEG29: LCD1.10 U1.A5 | length 2016.6
  Top Layer w3.94: v1(3338.15,1503.94) 3334.65,1503.94 3334.65,1501.96 3353.89,1482.72 3353.89,1462.15 U1.A5@3338.58,1446.85
  Signal Layer 3 w3.94: LCD1.10@1988.19,937.01 2041.06,989.88 2108.66,989.88 2125.68,1006.89 2518.7,1006.89 2577.76,1065.94 v1(2577.76,1193.9) ; v1(2602.3,1569.27) 2602.3,1572.77 2622.55,1593.02 2841.66,1593.02 2858.79,1575.88 3266.2,1575.88 v1(3338.15,1503.94)
  Signal Layer 4 w3.94: v1(2577.76,1193.9) 2603.07,1219.21 2603.07,1568.5 v1(2602.3,1569.27)
LCD_SEG30: LCD1.11 U1.B5 | length 1561.6
  Top Layer w3.94: v1(3322.85,1431.09) U1.B5@3338.58,1415.35 ; v1(3322.85,1431.09) 3325.57,1428.42 v1@3325.36,1428.95
  Signal Layer 3 w3.94: LCD1.11@2066.93,937.01 2126.97,997.05 2527.56,997.05 2637.99,1107.48 2637.99,1165.39 2787.01,1314.41 3103.78,1314.41 3138.23,1348.86 3138.23,1396.07 3188.62,1446.46 3307.48,1446.46 v1(3322.85,1431.09)
LCD_SEG31: LCD1.12 U1.C5 | length 1433.1
  Top Layer w3.94: v1(3322.85,1399.59) U1.C5@3338.58,1383.86
  Signal Layer 3 w3.94: LCD1.12@2148.62,942.91 2151.57,942.91 2196.85,988.19 2534.45,988.19 2651.46,1105.2 2651.46,1158.66 2799.33,1306.54 3107.04,1306.54 3146.52,1346.02 3159.01,1346.02 3190.51,1377.52 3190.51,1383.41 3222.01,1414.91 3307.54,1414.91 v1(3322.85,1399.59)
LCD_SEG32: LCD1.13 U1.E4 | length 1284
  Top Layer w3.94: v1(3291.35,1336.59) U1.E4@3307.09,1320.87 ; v1(3291.35,1336.59) 3294.07,1333.92 3299.79,1328.16
  Signal Layer 3 w3.94: LCD1.13@2224.41,937.01 2226.46,939.06 2265.83,939.06 2268.7,941.93 2268.7,949.8 2271.65,952.76 ; 2271.61,952.8 2289.29,970.47 2547.24,970.47 2801.18,1224.41 3143.7,1224.41 3163.39,1244.09 3177.2,1244.09 3190.54,1257.44 3233.84,1257.44 3291.35,1314.94 v1(3291.35,1336.59)
LCD_SEG33: LCD1.14 U1.F1 | length 1068.8
  Top Layer w3.94: v1(3170.82,1228.35) 3169.29,1228.35 3169.29,1246.06 U1.F1@3212.6,1289.37
  Signal Layer 3 w3.94: LCD1.14@2303.15,937.01 2327.76,961.61 2553.98,961.61 2808.9,1216.54 3157.48,1216.54 3169.29,1228.35 v1(3170.82,1228.35)
LCD_SEG34: LCD1.15 U1.F2 | length 1484.2
  Top Layer w3.94: v1(3177.17,1299.21) 3181.1,1299.21 3189.87,1307.98 3225.49,1307.98 U1.F2@3244.09,1289.37
  Signal Layer 3 w3.94: LCD1.15@2303.15,1937.01 2774.61,1937.01 2851.73,1859.88 v1(3062.76,1859.88)
  Signal Layer 4 w3.94: v1(3062.76,1859.88) 3062.76,1855.62 3055.12,1847.98 3055.12,1576.77 3145.67,1486.22 3145.67,1443.96 3169.05,1420.57 3169.05,1334.65 3177.17,1326.54 v1(3177.17,1299.21)
LCD_SEG35: LCD1.16 U1.H4 | length 2126.3
  Top Layer w3.94: U1.H4@3307.09,1226.38 v1(3322.85,1242.09)
  Signal Layer 4 w3.94: LCD1.16@2224.41,1937.01 2257.87,1903.54 2480.31,1903.54 2534.8,1958.03 2775.94,1958.03 2905.51,2087.6 3326.93,2087.6 3374.91,2039.62 3374.91,1888.49 3377.52,1885.89 3377.52,1637.36 3358.27,1618.11 3358.27,1557.09 3385.22,1530.13 3385.22,1488.88 3346.46,1450.11 3346.46,1321.56 3338.99,1314.09 3338.99,1258.24 v1(3322.85,1242.09)
LCD_SEG36: LCD1.17 U1.H5 | length 2163.7
  Top Layer w3.94: v1@3322.85,1210.64 U1.H5@3338.58,1226.38
  Signal Layer 4 w3.94: LCD1.17@2145.67,1937.01 2147.72,1934.96 2185.12,1934.96 2190.94,1929.13 2190.94,1915.35 2210.63,1895.67 2494.49,1895.67 2547.67,1948.85 2783.49,1948.85 2913.39,2078.74 3293.42,2078.74 3315.83,2056.32 3315.83,1757.73 3322.41,1751.16 3322.41,1452.57 3307.52,1437.69 3307.52,1229.75 3322.85,1214.42 v1(3322.85,1210.59)
LCD_SEG37: LCD1.18 U1.J5 | length 2359.3
  Top Layer w3.94: v1(3322.85,1179.09) 3338.58,1194.83 U1.J5@3338.58,1194.88
  Signal Layer 4 w3.94: LCD1.18@2066.93,1937.01 2103.17,1973.25 2774.43,1973.25 2899.61,2098.43 3331.08,2098.43 3431.52,1997.98 3431.52,1633.6 3393.1,1595.18 3393.1,1485.62 3354.33,1446.85 3354.33,1318.3 3346.86,1310.83 3346.86,1206.8 3322.85,1182.78 v1(3322.85,1179.09)
LCD_SEG38: LCD1.19 U1.J6 | length 2465.8
  Top Layer w3.94: U1.J6@3370.08,1194.88 v1(3385.85,1179.09)
  Signal Layer 4 w3.94: LCD1.19@1988.19,1937.01 2036.03,1984.85 2769.3,1984.85 2893.7,2109.25 3331.38,2109.25 3439.4,2001.24 3439.4,1630.34 3409.01,1599.96 3409.01,1444.41 3402.04,1437.44 3402.04,1425.63 3392.19,1415.78 3380.38,1415.78 3370.54,1405.94 3370.54,1354.66 3385.36,1339.83 3385.36,1288.55 3377.52,1280.71 3377.52,1245.63 3370.54,1238.65 3370.54,1199.88 3385.85,1184.57 v1(3385.85,1179.09)
LCD_SEG39: LCD1.20 U1.K5 | length 2196.2
  Top Layer w3.94: U1.K5@3338.56,1163.45 U1.K5@3338.6,1163.41 ; U1.K5@3338.58,1163.39 v1(3354.35,1147.59)
  Signal Layer 3 w3.94: LCD1.20@1909.45,1937.01 1950.79,1978.35 2750,1978.35 2849.9,1878.45 3095.96,1878.45 3113.19,1861.22 3214.57,1861.22 v1(3216.54,1863.19)
  Signal Layer 4 w3.94: v1(3216.54,1863.19) 3216.54,1561.36 3234.05,1543.85 3234.05,1489.68 3251.53,1472.2 3251.53,1451.46 3244.55,1444.48 3244.55,1424.81 3253.52,1415.84 3265.26,1415.84 3275.59,1405.51 3275.59,1322.83 3299.21,1299.21 3299.21,1177.17 3312.59,1163.78 3338.16,1163.78 v1(3354.35,1147.59)
LED_JLINK: LED901.2 TPJ912.1 U900.A7 | length 2255.4
  Top Layer w3.94: U900.A7@1680.12,1497.05 1680.12,1477.18 1673.08,1470.14 1673.08,1457.1 1677.17,1453.01 1677.17,1419.84 1673.08,1415.75 1673.08,1391.55 1682.14,1382.49 1682.61,1382.49 1692.91,1372.19 1692.91,1320.86 1682.69,1310.64 1682.69,1308.42 v2@1683.02,1308.09
  Top Layer w4: LED901.2@213.78,1775.98 226.38,1763.39 v1(226.38,1742.13)
  Signal Layer 3 w3.94: v1@227.36,1743.11 228.35,1742.13 552.82,1742.13 958.33,1336.61 1280.51,1336.61 1295,1351.1 1486.99,1351.1 1526.99,1311.1 1541.41,1311.1 1547.11,1305.4 v2(1677.44,1305.4) 1702.11,1305.4 1708.44,1311.73 1799.95,1311.73 1814.15,1297.52 1950.27,1297.52 v1(1973.61,1320.87)
  Bottom Layer w3.94: v1(1973.61,1320.87) 1993.07,1320.87 1998.3,1326.1 1998.3,1347.17 TPJ912.1@1998.03,1347.44 TPJ912.1@1998.03,1345.28
LED_STATUS_G: LED904.3 U900.D13 | length 1080.8
  Top Layer w3.94: LED904.3@686.57,1819.29 708.28,1819.29 731.69,1795.88 v1(731.69,1722.4) ; v2(1501.26,1555.12) 1505.61,1555.12 1513.11,1562.61 1554.6,1562.61 1561.11,1556.1 U900.D13@1562.01,1556.1
  Signal Layer 3 w3.94: v1(731.69,1722.4) 720,1710.71 720,1688.03 787.51,1620.53 800.08,1607.95 923.22,1607.95 935.79,1620.53 1365.7,1620.53 1431.1,1555.12 v2(1501.26,1555.12)
LED_STATUS_R: LED904.4 U900.E13 | length 1008.4
  Top Layer w3.94: LED904.4@686.57,1791.73 692.48,1791.73 698.39,1785.83 714.33,1769.88 714.33,1718.11 740.55,1691.89 v1(740.55,1690.51) ; v2(1537.98,1587.01) 1541.06,1583.94 1553.86,1583.94 U900.E13@1562.01,1575.79
  Signal Layer 3 w3.94: v1(740.55,1690.51) 798.22,1632.85 813.19,1617.87 914.88,1617.87 929.85,1632.85 942.52,1632.85 1368.14,1632.85 1413.97,1587.01 v2(1537.98,1587.01)
LES_LC_SENSE: J101.20 R196.1 U1.G11 | length 3477.5
  Top Layer w3.94: U1.G11@3527.56,1257.87 3545.28,1257.87 v1(3555.12,1248.03) ; R196.1@4234.96,263.5 4235.59,262.87 4235.59,248.66 v1(4236.22,248.03)
  Signal Layer 3 w3.94: v1(3401.57,177.17) 3872.05,177.17 3942.91,248.03 v1(4236.22,248.03)
  Signal Layer 4 w3.94: J101.20@2118.5,228.43 2165.35,181.57 2165.35,110.24 2200.79,74.8 2751.97,74.8 2809.06,131.89 3356.3,131.89 v1(3401.57,177.17) 3527.56,303.15 3527.56,1149.61 3531.5,1153.54 3531.5,1225.28 3554.25,1248.03 v1(3555.12,1248.03)
LES_LIGHT_EXCITE: Q100.1 R307.2 | length 51
  Top Layer w3.94: R307.2@4312.99,1913.39 4361.22,1913.39 Q100.1@4363.19,1915.35
LES_LIGHT_SENSE: J101.18 Q100.2 R199.1 U1.G10 | length 4235.8
  Top Layer w3.94: U1.G10@3496.06,1257.87 v1(3511.85,1242.09) ; v1(4236.22,1976.38) 4361.22,1976.38 Q100.2@4363.19,1978.35
  Signal Layer 3 w3.94: v1@3511.85,1244.13 v1(3511.85,1242.09) 3544.86,1275.11 3842.59,1275.11 4065.24,1497.76 4107.6,1497.76 4183.07,1573.23 4183.07,1927.17 4232.28,1976.38 v1(4236.22,1976.38)
  Signal Layer 4 w3.94: J101.18@2018.5,228.43 2066.93,180 2066.93,110.24 2115.16,62.01 2758.82,62.01 2812.95,116.14 3375.98,116.14 3562.99,303.15 3562.99,857.83 3585.47,880.32 3585.47,1012.69 ; v1(3511.85,1242.09) 3533.53,1263.78 3574.8,1263.78 3625.51,1213.07 3625.51,1052.73 3585.47,1012.69 ; 3595.49,1022.71 3585.47,1012.69
LFXTAL_N: C422.1 U1.L1 X2.1 | length 129.7
  Top Layer w7.87: C422.1@3113.19,1086.61 3113.19,1108.27 X2.1@3124.02,1119.09 ; X2.1@3125,1119.49 3136.23,1119.49 3148.62,1131.89 U1.L1@3212.6,1131.89
LFXTAL_P: C421.1 U1.K1 X2.2 | length 137.5
  Top Layer w7.87: C421.1@3113.19,1211.61 3113.19,1188.98 X2.2@3124.02,1178.15 3136.88,1178.15 3157.55,1157.48 3205.09,1157.48 3211,1163.39 U1.K1@3212.6,1163.39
